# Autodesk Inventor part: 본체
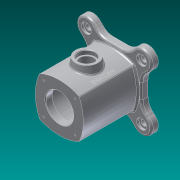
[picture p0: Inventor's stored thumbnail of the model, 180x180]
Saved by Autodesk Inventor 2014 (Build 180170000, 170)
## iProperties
Created: 2016-05
Part Number: 본체
Material: 알루미늄 6061
Document SubType Name: Modeling
Designer: Administrator
Density: 2.71 g/cm^3
Appearance: 알루미늄 - 평지
Mass: 1113.81 g
Surface Area: 865.194 cm^2
Volume: 411.001 cm^3
Author: Administrator
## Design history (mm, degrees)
sketch "스케치2" dims "d0" = 100
  geometry: L1 (35.355, -35.355)-(-35.355, -35.355); L2 (-35.355, -35.355)-(-35.355, 35.355); L3 (-35.355, 35.355)-(35.355, 35.355); L4 (35.355, 35.355)-(35.355, -35.355); L5 (35.355, -35.355)-(-35.355, 35.355); L6 (-35.355, -35.355)-(35.355, 35.355); A1 r 85.579 centre (-42.579, 0) between (35.355, -35.355) and (35.355, 35.355); A2 r 85.579 centre (42.579, 0) between (-35.355, 35.355) and (-35.355, -35.355); A3 r 85.579 centre (0, -42.579) between (35.355, 35.355) and (-35.355, 35.355); A4 r 85.579 centre (0, 42.579) between (-35.355, -35.355) and (35.355, -35.355); 2 further points
  constraints: 12 end point, 8 point on circle, 4 centre point, 3 equal radius, 2 midpoint, 2 parallel, 2 perpendicular, 1 coincident, 1 horizontal, 3 other
  dimensions: "d1" = 86 dimension on A2 A1; "d2" = 86 dimension on A4 A3 (derived)
extrude "돌출1" new body sketch "스케치2" distance "d3" = 61; taper "d5" = 0 deg; dims "d4" = 49, "d6" = 0
sketch "스케치3"
  geometry: L1 (-49, 0)-(-37, 0); L2 (-37, 0)-(-37, 25); L3 (-37, 25)-(-49, 25); L4 (-49, 25)-(-49, 0); L5 (-37, 0)-(49, 0); L6 (49, 0)-(49, 35); L7 (49, 35)-(-37, 35); L8 (-37, 35)-(-37, 0); L9 (49, 0)-(61, 0); L10 (61, 0)-(61, 25); L11 (61, 25)-(49, 25); L12 (49, 25)-(49, 0); L13 (-49, 35.355)-(-49, -35.355) reference; L14 (61, -35.355)-(61, 35.355) reference; L15 (-71, 0)-(83, 0) reference; 1 further point
  constraints: 24 end point, 6 parallel, 3 horizontal, 3 perpendicular, 2 midpoint
  dimensions: "d7" = 70 diameter of L7 L5; "d8" = 50 diameter of L11 L5; "d9" = 50 diameter of L3 L5; "d10" = 12 distance between parallel lines of L4 L2; "d11" = 12 distance between parallel lines of L14 L6; "d12" = 86 distance between parallel lines of L12 L2 (derived)
revolve "회전1" sketch "스케치3" stored, may be unused: angle "d13" = 90 deg
sketch "스케치4"
  geometry: L1 (-98, 0)-(98, 0) reference; L2 (49.497, -49.497)-(0, 0); L3 (60.483, -35.239)-(41.451, -16.207); L4 (35.239, -60.483)-(16.207, -41.451); L5 (41.451, -16.207)-(16.207, -41.451); A1 r 70 centre (0, 0) between (49.497, -49.497) and (60.483, -35.239); A2 r 18 centre (49.497, -49.497) between (60.483, -35.239) and (35.239, -60.483); A3 r 85.579 centre (-42.579, 0) between (35.355, -35.355) and (35.355, 35.355) reference; 1 further point
  constraints: 8 end point, 6 point on circle, 2 centre point, 2 parallel, 1 coincident, 1 perpendicular
  dimensions: "d15" = 70 radius of A1; "d17" = 45 deg angle of L1 L2; "d21" = 18 radius of A2
extrude "돌출2" join sketch "스케치4" distance "d18" = 12; taper "d19" = 0 deg
sketch "스케치7"
  geometry: L1 (49, 49)-(-49, 49); L2 (-49, 49)-(-49, -49); L3 (-49, -49)-(49, -49); L4 (49, -49)-(49, 49); L5 (49, 49)-(-49, -49); L6 (-49, 49)-(49, -49); L7 (60.483, -35.239)-(41.451, -16.207) reference; L8 (16.207, -41.451)-(35.239, -60.483) reference; A1 r 85.579 centre (-42.579, 0) between (41.451, -16.207) and (35.355, 35.355) reference; A2 r 85.579 centre (0, 42.579) between (-35.355, -35.355) and (16.207, -41.451) reference; A3 r 85.579 centre (42.579, 0) between (-35.355, 35.355) and (-35.355, -35.355) reference; A4 r 85.579 centre (0, -42.579) between (35.355, 35.355) and (-35.355, 35.355) reference; 3 further points
  constraints: 12 end point, 4 point on line, 2 midpoint, 2 parallel, 2 perpendicular, 1 horizontal
  dimensions: "d58" = 98 distance of L1.start L1.end
extrude "돌출4" join sketch "스케치7" distance "d59" = 12; taper "d60" = 0 deg
hole "구멍1" diameter "d24" = 10; stored, may be unused: countersink angle "d28" = 90 deg, drill point angle "d30" = 0 deg; dims "d22" = 10, "d23" = 10, "d25" = 6, "d26" = 18, "d27" = 4, "d29" = 8
sketch "스케치5" dims "d34" = 40
  geometry: L1 (0, 0)-(28.284, -28.284); L2 (-98, 0)-(98, 0) reference; 1 further point
  constraints: 2 end point, 1 coincident, 3 other
  dimensions: "d32" = 45 deg angle of L2 L1 (= d17)
hole "구멍2" sketch "스케치5" at (28.284, -28.284) diameter "d35" = 3.242; stored, may be unused: countersink angle "d39" = 90 deg, drill point angle "d41" = 118 deg; dims "d36" = 7, "d37" = 18, "d38" = 4, "d40" = 10
node "작업 평면1"
sketch "스케치6"
  geometry: C1 r 20 at (0, 0); 1 further point
  constraints: 1 centre point, 1 coincident
  dimensions: "d46" = 40 diameter of C1
extrude "돌출3" join sketch "스케치6" stored distance "d47" = 12; taper "d48" = 10 deg
hole "구멍3" diameter "d51" = 25; stored, may be unused: countersink angle "d55" = 90 deg, drill point angle "d57" = 0 deg; dims "d49" = 10, "d50" = 10, "d52" = 7, "d53" = 30, "d54" = 8, "d56" = 10
fillet "모깎기1" dims "d61" = 25
fillet "모깎기2" dims "d62" = 3
fillet "모깎기3" dims "d63" = 3
fillet "모깎기5" dims "d65" = 3
fillet "모깎기6" dims "d66" = 3
chamfer "모따기1" distance "d67" = 1; stored, may be unused: second distance "d68" = 2, angle "d69" = 45 deg
chamfer "모따기2" distance "d70" = 1; stored, may be unused: second distance "d71" = 2, angle "d72" = 45 deg
chamfer "모따기3" distance "d73" = 1; stored, may be unused: second distance "d74" = 2, angle "d75" = 45 deg
sketch "스케치8" dims "d76" = 40
  geometry: L1 (0, 0)-(-28.284, 28.284); L2 (-94.496, 0)-(94.496, 0) reference; 1 further point
  constraints: 2 end point, 1 coincident, 3 other
  dimensions: "d77" = 45 deg angle of L1 L2
hole "구멍4" sketch "스케치8" at (-28.284, 28.284) diameter "d78" = 3.242; stored, may be unused: countersink angle "d82" = 90 deg, drill point angle "d84" = 118 deg; dims "d79" = 7, "d80" = 19.05, "d81" = 4.775, "d83" = 10
sketch "스케치10"
  geometry: L1 (-34.285, -49)-(34.285, -49) reference; 2 further points
  constraints: 1 other
  dimensions: "d90" = 49 distance from line of L1 point (29, 0); "d91" = 29 distance of point (29, 0) point (0, 0)
feature "엠보싱1" sketch "스케치10" dims "d0" = 100, "d1" = 86, "d2" = 86 (derived), "d7" = 70, "d8" = 50, "d9" = 50, "d10" = 12, "d11" = 12, "d12" = 86 (derived), "d92" = 0.5, "d93" = 0
fillet "모깎기7" dims "d94" = 3
node "솔리드1"
pattern_circular "원형 패턴1" dims "d43" = 360 deg
pattern_circular "원형 패턴2" dims angle "d86" = 360 deg
other parameters: "d45" = 55
